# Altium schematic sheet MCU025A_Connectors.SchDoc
size 431 x 279 mm; Date: Not shown in title block; ApprovedBy: Not shown in title block; CheckedBy: Not shown in title block; Author: Not shown in title block; CompanyName: Not shown in title block; Engineer: Not shown in title block; Organization: Not shown in title block; Address1: Not shown in title block; Address2: Not shown in title block; Address3: Not shown in title block; Address4: Not shown in title block; DocumentNumber: 2; Revision: Use project parameter SCH_Rev; SheetNumber: 2; SheetTotal: 8; PageSetup: Record=PageOptions¦CenterHorizontal=True¦CenterVertical=True¦PrintScale=1.00¦XCorrection=1.00¦YCorrection=1.00¦PrintKind=0¦BorderSize=5000000¦LeftOffset=0¦BottomOffset=0¦Orientation=2¦PaperLength=1000¦PaperWidth=1000¦Scale=100¦PaperSource=15¦PrintQuality=600¦MediaType=1¦DitherType=10¦PaperKind=Letter¦PrintScaleMode=1
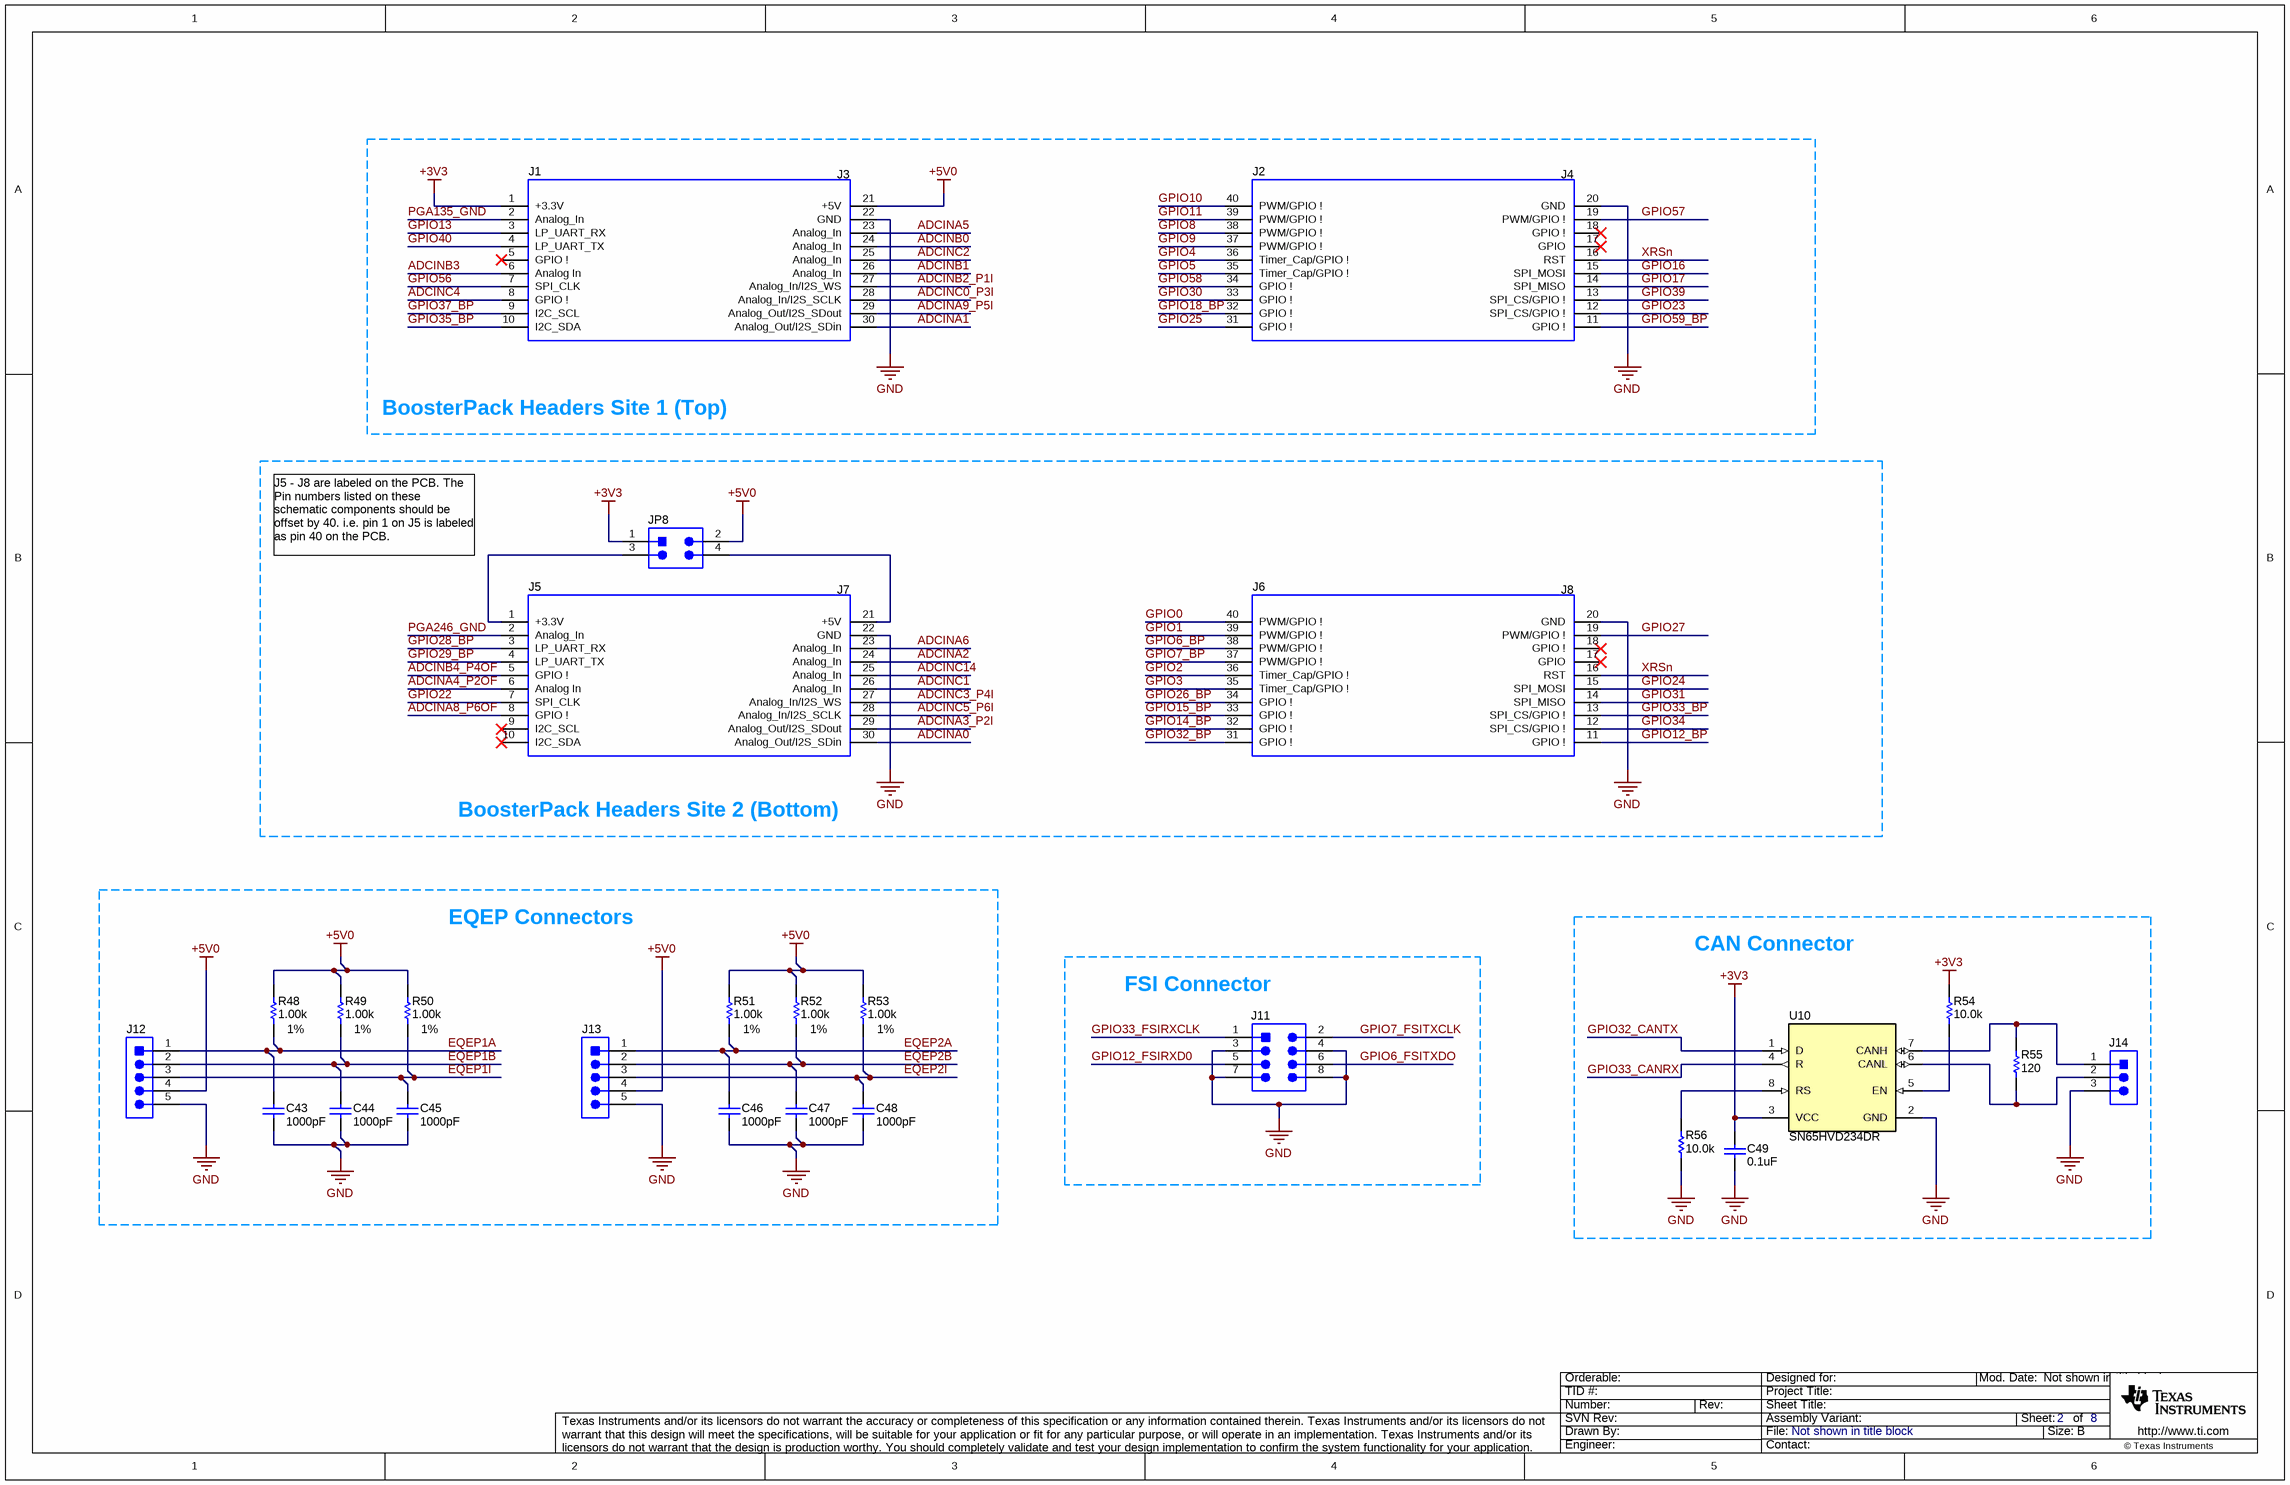
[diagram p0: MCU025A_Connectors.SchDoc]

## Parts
C43  ValueDisplayed: 1000pF  [0402]  (hidden comment: GRM155R71H102KA01D)
C44  ValueDisplayed: 1000pF  [0402]  (hidden comment: GRM155R71H102KA01D)
C45  ValueDisplayed: 1000pF  [0402]  (hidden comment: GRM155R71H102KA01D)
C46  ValueDisplayed: 1000pF  [0402]  (hidden comment: GRM155R71H102KA01D)
C47  ValueDisplayed: 1000pF  [0402]  (hidden comment: GRM155R71H102KA01D)
C48  ValueDisplayed: 1000pF  [0402]  (hidden comment: GRM155R71H102KA01D)
C49  ValueDisplayed: 0.1uF  [0402]  (hidden comment: GRM155R71A104KA01D)
J1  SSQ-110-03-T-D  [BoosterPack_40pin_J1J3]  (value not drawn)
J2  SSQ-110-03-T-D  [BoosterPack_40pin_J2J4]  (value not drawn)
J5  SSQ-110-03-T-D  [BoosterPack_40pin_J1J3]  (value not drawn)
J6  SSQ-110-03-T-D  [BoosterPack_40pin_J2J4]  (value not drawn)
J11  TSW-104-07-G-D  [TSW-104-07-G-D]  (value not drawn)
J12  TSW-105-07-G-S  [TSW-105-07-X-S]  (value not drawn)
J13  TSW-105-07-G-S  [TSW-105-07-X-S]  (value not drawn)
J14  61300311121  [WURTH_61300311121]  (value not drawn)
JP8  TSW-102-07-G-D  [TSW-102-07-G-D]  (value not drawn)
R48  ValueDisplayed: 1.00k  Value1: 1%  [0402]  (hidden comment: CRCW04021K00FKED)
R49  ValueDisplayed: 1.00k  Value1: 1%  [0402]  (hidden comment: CRCW04021K00FKED)
R50  ValueDisplayed: 1.00k  Value1: 1%  [0402]  (hidden comment: CRCW04021K00FKED)
R51  ValueDisplayed: 1.00k  Value1: 1%  [0402]  (hidden comment: CRCW04021K00FKED)
R52  ValueDisplayed: 1.00k  Value1: 1%  [0402]  (hidden comment: CRCW04021K00FKED)
R53  ValueDisplayed: 1.00k  Value1: 1%  [0402]  (hidden comment: CRCW04021K00FKED)
R54  ValueDisplayed: 10.0k  [0402]  (hidden comment: CRCW040210K0FKED)
R55  ValueDisplayed: 120  [0603]  (hidden comment: RC0603FR-07120RL)
R56  ValueDisplayed: 10.0k  [0402]  (hidden comment: CRCW040210K0FKED)
U10  SN65HVD234DR  [D0008A_L]

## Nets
+3V3: C49.2 J1.1(+3.3V) JP8.1 R54.2 U10.3(VCC)
+5V0: J1.21(+5V) J12.4 J13.4 JP8.2 R48.2 R49.2 R50.2 R51.2 R52.2 R53.2
GND: C43.2 C44.2 C45.2 C46.2 C47.2 C48.2 C49.1 J1.22(GND) J2.20(GND) J5.22(GND) J6.20(GND) J11.3 J11.4 J11.7 J11.8 J12.5 J13.5 J14.3 R56.1 U10.2(GND)
ADCINA0: J5.30(Analog_Out/I2S_SDin)
ADCINA1: J1.30(Analog_Out/I2S_SDin)
ADCINA2: J5.24(Analog_In)
ADCINA3_P2I: J5.29(Analog_Out/I2S_SDout)
ADCINA4_P2OF: J5.6(Analog_In)
ADCINA5: J1.23(Analog_In)
ADCINA6: J5.23(Analog_In)
ADCINA8_P6OF: J5.8(GPIO_!)
ADCINA9_P5I: J1.29(Analog_Out/I2S_SDout)
ADCINB0: J1.24(Analog_In)
ADCINB1: J1.26(Analog_In)
ADCINB2_P1I: J1.27(Analog_In/I2S_WS)
ADCINB3: J1.6(Analog_In)
ADCINB4_P4OF: J5.5(GPIO_!)
ADCINC0_P3I: J1.28(Analog_In/I2S_SCLK)
ADCINC1: J5.26(Analog_In)
ADCINC2: J1.25(Analog_In)
ADCINC3_P4I: J5.27(Analog_In/I2S_WS)
ADCINC4: J1.8(GPIO_!)
ADCINC5_P6I: J5.28(Analog_In/I2S_SCLK)
ADCINC14: J5.25(Analog_In)
EQEP1A: C43.1 J12.1 R48.1
EQEP1B: C44.1 J12.2 R49.1
EQEP1I: C45.1 J12.3 R50.1
EQEP2A: C46.1 J13.1 R51.1
EQEP2B: C47.1 J13.2 R52.1
EQEP2I: C48.1 J13.3 R53.1
GPIO0: J6.40(PWM/GPIO_!)
GPIO1: J6.39(PWM/GPIO_!)
GPIO2: J6.36(Timer_Cap/GPIO_!)
GPIO3: J6.35(Timer_Cap/GPIO_!)
GPIO4: J2.36(Timer_Cap/GPIO_!)
GPIO5: J2.35(Timer_Cap/GPIO_!)
GPIO6_BP: J6.38(PWM/GPIO_!)
GPIO6_FSITXDO: J11.6
GPIO7_BP: J6.37(PWM/GPIO_!)
GPIO7_FSITXCLK: J11.2
GPIO8: J2.38(PWM/GPIO_!)
GPIO9: J2.37(PWM/GPIO_!)
GPIO10: J2.40(PWM/GPIO_!)
GPIO11: J2.39(PWM/GPIO_!)
GPIO12_BP: J6.11(GPIO_!)
GPIO12_FSIRXD0: J11.5
GPIO13: J1.3(LP_UART_RX)
GPIO14_BP: J6.32(GPIO_!)
GPIO15_BP: J6.33(GPIO_!)
GPIO16: J2.15(SPI_MOSI)
GPIO17: J2.14(SPI_MISO)
GPIO18_BP: J2.32(GPIO_!)
GPIO22: J5.7(SPI_CLK)
GPIO23: J2.12(SPI_CS/GPIO_!)
GPIO24: J6.15(SPI_MOSI)
GPIO25: J2.31(GPIO_!)
GPIO26_BP: J6.34(GPIO_!)
GPIO27: J6.19(PWM/GPIO_!)
GPIO28_BP: J5.3(LP_UART_RX)
GPIO29_BP: J5.4(LP_UART_TX)
GPIO30: J2.33(GPIO_!)
GPIO31: J6.14(SPI_MISO)
GPIO32_BP: J6.31(GPIO_!)
GPIO32_CANTX: U10.1(D)
GPIO33_BP: J6.13(SPI_CS/GPIO_!)
GPIO33_CANRX: U10.4(R)
GPIO33_FSIRXCLK: J11.1
GPIO34: J6.12(SPI_CS/GPIO_!)
GPIO35_BP: J1.10(I2C_SDA)
GPIO37_BP: J1.9(I2C_SCL)
GPIO39: J2.13(SPI_CS/GPIO_!)
GPIO40: J1.4(LP_UART_TX)
GPIO56: J1.7(SPI_CLK)
GPIO57: J2.19(PWM/GPIO_!)
GPIO58: J2.34(GPIO_!)
GPIO59_BP: J2.11(GPIO_!)
PGA135_GND: J1.2(Analog_In)
PGA246_GND: J5.2(Analog_In)
XRSn: J2.16(RST) J6.16(RST)
NetJ5_1: J5.1(+3.3V) JP8.3
NetJ5_21: J5.21(+5V) JP8.4
NetJ14_1: J14.1 R55.2 U10.7(CANH)
NetJ14_2: J14.2 R55.1 U10.6(CANL)
NetR54_1: R54.1 U10.5(EN)
NetR56_2: R56.2 U10.8(RS)

Not connected (* = marked no-connect by the designer): J1 5(GPIO_!)*; J2 17(GPIO)* 18(GPIO_!)*; J5 9(I2C_SCL)* 10(I2C_SDA)*; J6 17(GPIO)* 18(GPIO_!)*

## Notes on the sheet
- (near J1) J3
- (near J2) J4
- BoosterPack Headers Site 1 (Top)
- J5 - J8 are labeled on the PCB. The Pin numbers listed on these schematic components should be offset by 40. i.e. pin 1 on J5 is labeled as pin 40 on the PCB.
- (near J5) J7
- (near J6) J8
- BoosterPack Headers Site 2 (Bottom)
- EQEP Connectors
- CAN Connector
- (near J11) FSI Connector

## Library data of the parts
C43-C48 = CMP-0006673-2: CAP, CERM, 1000 pF, 50 V, +/- 10%, X7R, 0402; Manufacturer: MuRata; Polarized: N; Value: 1000pF; U/M: EA; Cap_F: 1nF; Value1: Unknown; VDC_V: 50V; TaMin_C: -55°C; TaMax_C: 125°C; SizeArea_mm2: 0.5; SizeAreaWB_mm2: 3; SizeX_mm: 1; SizeZ_mm: 0.6; AEC Category: Q200
C49 = CMP-0006629-2: CAP, CERM, 0.1 uF, 10 V, +/- 10%, X7R, 0402; Manufacturer: MuRata; Polarized: N; Value: 0.1uF; U/M: EA; Cap_F: 100nF; Value1: Unknown; VDC_V: 10V; TaMin_C: -55°C; TaMax_C: 125°C; SizeArea_mm2: 0.5; SizeAreaWB_mm2: 3; SizeX_mm: 1; SizeZ_mm: 0.6; AEC Category: Q200
J1 J5 = CMP-0003837-2: Receptacle, 2.54mm, 10x2, Tin, TH; Manufacturer: Samtec; Alternate Manufacturer: Major League Electronics; Alternate PartNumber: CRD-081413-A-G; Note: Booster Pack 40 pin J1 and J3; Green_Lifecycle: Active; Green_REACh: Incomplete
J2 J6 = CMP-0078266-2: Receptacle, 2.54mm, 10x2, Tin, TH; Manufacturer: Samtec; Alternate Manufacturer: Major League Electronics; Alternate PartNumber: CRD-081413-A-G; Note: Booster Pack 40 pin J2 and J4; Green_Lifecycle: Active; Green_REACh: Incomplete
J11 = CMP-0075408-1: Header, 100mil, 4x2, Gold, TH; Manufacturer: Samtec; Pitch_mm: 2.54; Cert_VDE: N; Gender: Male; Cert_CSA: Y; Voltage_V: 550V; Green_REACh: Passed; Current_A: 6.3A; CT: False; Green_Lifecycle: Active; Row_Count: 2; CNHeader: True
J12 J13 = CMP-0075411-1: Header, 100mil, 5x1, Gold, TH; Manufacturer: Samtec; Pitch_mm: 2.54; Cert_VDE: N; Gender: Male; Cert_CSA: Y; Voltage_V: 550V; Green_REACh: Passed; Current_A: 6.3A; CT: False; Green_Lifecycle: Active; Row_Count: 1; CNHeader: True
J14 = CMP-0054796-1: Header, 2.54 mm, 3x1, Gold, TH; Manufacturer: Wurth Elektronik; Green_Lifecycle: Active; Green_REACh: Passed; CNHeader: TRUE; CT: FALSE
JP8 = CMP-0075404-1: Header, 100mil, 2x2, Gold, TH; Manufacturer: Samtec; CNHeader: True; Shrouded: N; Gender: Male; Row_Count: 2; RowSpacing_mm: 2.54; CT: False; Cert_CSA: Y; Current_A: 6.3A; Green_Lifecycle: Active; Green_REACh: Passed; Voltage_V: 550V
R48-R53 = CMP-0026071-3: RES, 1.00 k, 1%, 0.063 W, AEC-Q200 Grade 0, 0402; Manufacturer: Vishay-Dale; Value: 1.00k; Res_ohm: 1k; Value_Code: 1k00; Power_W: 63mW; Value2: 0.063W; VDC_V: 50V; TempCo: 100 ppm/C; SizeArea_mm2: 0.5; SizeX_mm: 1; SizeZ_mm: 0.6; EIA_Code: E96; AEC Category: Q200; AEC Qualified: Y; AEC Grade: 0
R54 R56 = CMP-0025958-3: RES, 10.0 k, 1%, 0.063 W, AEC-Q200 Grade 0, 0402; Manufacturer: Vishay-Dale; Value: 10.0k; Res_ohm: 10k; Value_Code: 10k0; Power_W: 63mW; Value2: 0.063W; VDC_V: 50V; TempCo: 100 ppm/C; SizeArea_mm2: 0.5; SizeX_mm: 1; SizeZ_mm: 0.6; EIA_Code: E96; AEC Category: Q200; AEC Qualified: Y; AEC Grade: 0
R55 = CMP-0022769-3: RES, 120, 1%, 0.1 W, 0603; Manufacturer: Yageo America; Value: 120; Value_Code: 120R; Power_W: 100mW; Value2: 0.1W; VDC_V: 150V; TempCo: 200 ppm/C; SizeArea_mm2: 1.28; SizeX_mm: 1.6; SizeY_mm: 0.8; SizeZ_mm: 1; U/M: EA; AEC Category: Q200
U10 = CMP-0033355-1: 3.3V CAN Transceiver with Sleep Mode, 6 mA, -40 to 125 degC, 8-pin SOIC (D), Green (RoHS & no Sb/Br); Manufacturer: Texas Instruments; Drivers Per Package: 1; Bus Fault Voltage(V): +/-30; Transient Pulse Protection(V): -100 to 100; ICC(Max)(mA): 6; Supply Voltage(s)(V): 3.3; Rating: Catalog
